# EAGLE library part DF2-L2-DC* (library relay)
HIGHLY SENSITIVE DIP MINIATURE RELAY NAiS 2 coil latching Set/Reset Source: http://www.mew-europe.com/.. en_ds_61002_0000.pdf
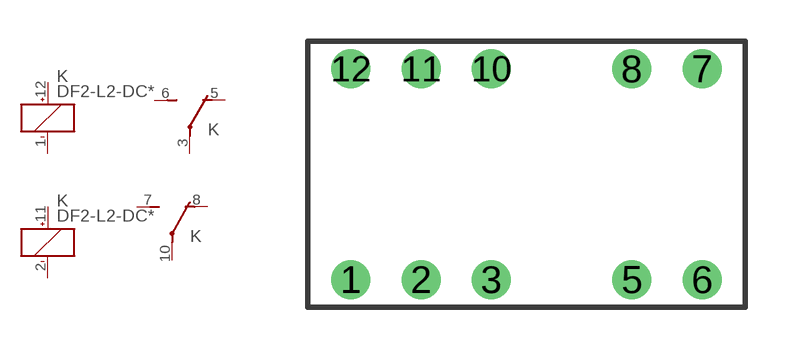
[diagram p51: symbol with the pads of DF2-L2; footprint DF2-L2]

Designator prefix K; gates S=K+- R=K+- 3=U 4=U

## DF2-L2-DC1.5V (OC_FARNELL: unknown; OC_NEWARK: unknown), DF2-L2-DC3V (OC_FARNELL: unknown; OC_NEWARK: unknown), DF2-L2-DC5V (OC_FARNELL: unknown; OC_NEWARK: unknown), DF2-L2-DC6V (OC_FARNELL: unknown; OC_NEWARK: unknown), DF2-L2-DC9V (OC_FARNELL: unknown; OC_NEWARK: unknown), DF2-L2-DC12V (OC_FARNELL: unknown; OC_NEWARK: unknown), DF2-L2-DC24 (OC_FARNELL: unknown; OC_NEWARK: unknown)  [DF2-L2]
1  S:-  pas
2  R:-  pas
3  3:P  pas
5  3:O  pas
6  3:S  pas
7  4:S  pas
8  4:O  pas
10  4:P  pas
11  R:+  pas
12  S:+  pas

## Footprint DF2-L2 (pad centres in mm)
HIGHLY SENSITIVE DIP MINIATURE RELAY 2 coil Source: http://www.mew-europe.com/.. en_ds_61002_0000.pdf
drill 0.9 round: 1 -6.35,-3.81; 2 -3.81,-3.81; 3 -1.27,-3.81; 5 3.81,-3.81; 6 6.35,-3.81; 7 6.35,3.81; 8 3.81,3.81; 10 -1.27,3.81; 11 -3.81,3.81; 12 -6.35,3.81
